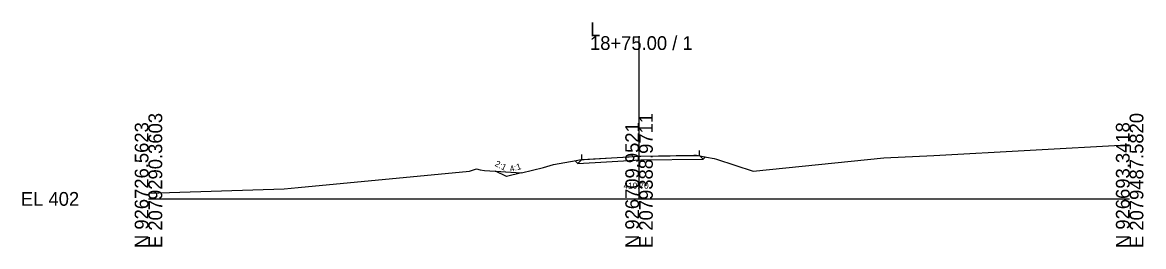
# Model space of a CAD drawing. Extents: x -26 to 10503, y -10 to 9546.
# Drawn here: x 974.3 to 1202.8, y 7490.3 to 7535.9 of the extents above; entities that cross this region are included whole.
import ezdxf

# ---------------------------------------------------------------- set-up
doc = ezdxf.new("R2010")
doc.units = 0
for name, color, linetype in [('Default', 7, 'Continuous'), ('Exist XS Center Line Elevation Label', 7, 'Continuous'), ('Exist XS Ground Line', 7, 'Continuous'), ('Old_Level_63', 7, 'Continuous'), ('Old_Level_8', 7, 'Continuous'), ('Prop XS DDE', 7, 'Continuous'), ('Prop XS EOT Tick Mark', 7, 'Continuous'), ('Prop XS Finish Grade Pavement', 7, 'Continuous'), ('Prop XS Side Slope Text', 7, 'Continuous'), ('Prop XS Subgrade Earthwork', 7, 'Continuous')]:
    doc.layers.add(name, color=color, linetype=linetype)

msp = doc.modelspace()

# ---------------------------------------------------------------- linework, layer by layer
at = {"layer": 'Default'}
for points in [[(1072.96, 7504.55), (1070.72, 7505.67), (1076.03, 7505.32)], [(1076.03, 7505.32), (1072.96, 7504.55), (1070.72, 7505.67)]]:
    msp.add_lwpolyline(points, close=True, dxfattribs=at)
at = {"layer": 'Exist XS Ground Line'}
for p, q in [((1160.07, 7508.82), (1199.33, 7511.01)), ((1199.33, 7511.01), (1200, 7511.03)), ((1082.56, 7507), (1087.18, 7507.8)), ((1087.18, 7507.8), (1088.19, 7507.99)), ((1088.19, 7507.99), (1088.84, 7508.03)), ((1088.84, 7508.03), (1100, 7508.7)), ((1100, 7508.7), (1100.33, 7508.72)), ((1100.33, 7508.72), (1111.14, 7508.89)), ((1111.14, 7508.89), (1111.73, 7508.9)), ((1111.73, 7508.9), (1113.78, 7508.51)), ((1113.78, 7508.51), (1115.32, 7508.23)), ((1115.32, 7508.23), (1115.76, 7508.07)), ((1115.76, 7508.07), (1123.24, 7505.63)), ((1123.24, 7505.63), (1149.87, 7508.36)), ((1149.87, 7508.36), (1160.07, 7508.82)), ((1030.53, 7502.31), (1065.43, 7505.64)), ((1065.43, 7505.64), (1066.86, 7506.1)), ((1066.86, 7506.1), (1067.64, 7505.88)), ((1067.64, 7505.88), (1068.52, 7505.81)), ((1068.52, 7505.81), (1076.03, 7505.32)), ((1076.03, 7505.32), (1080.52, 7506.38)), ((1080.52, 7506.38), (1082.56, 7507)), ((1000, 7501.17), (1027.63, 7502.04)), ((1027.63, 7502.04), (1030.53, 7502.31))]:
    msp.add_line(p, q, dxfattribs=at)
at = {"layer": 'Old_Level_63'}
for p, q in [((1100, 7500), (1100, 7533.1)), ((1000, 7500), (1100, 7500)), ((1100, 7500), (1200, 7500))]:
    msp.add_line(p, q, dxfattribs=at)
at = {"layer": 'Old_Level_8'}
for p, q in [((1088.33, 7508), (1087.53, 7507.2)), ((1112.33, 7508.84), (1113.07, 7508.1))]:
    msp.add_line(p, q, dxfattribs=at)
at = {"layer": 'Prop XS DDE'}
for p, q in [((1072.96, 7504.55), (1070.72, 7505.67)), ((1076.03, 7505.32), (1072.96, 7504.55))]:
    msp.add_line(p, q, dxfattribs=at)
at = {"layer": 'Prop XS EOT Tick Mark'}
for p, q in [((1112.33, 7508.84), (1112.33, 7509.84)), ((1088.33, 7508), (1088.33, 7509))]:
    msp.add_line(p, q, dxfattribs=at)
at = {"layer": 'Prop XS Finish Grade Pavement'}
for p, q in [((1088.33, 7508), (1100.33, 7508.72)), ((1100.33, 7508.72), (1112.33, 7508.84))]:
    msp.add_line(p, q, dxfattribs=at)
at = {"layer": 'Prop XS Subgrade Earthwork'}
for p, q in [((1087.53, 7507.2), (1086.96, 7507.76)), ((1087.53, 7507.2), (1100.37, 7507.97)), ((1100.37, 7507.97), (1113.07, 7508.1)), ((1113.07, 7508.1), (1113.54, 7508.56))]:
    msp.add_line(p, q, dxfattribs=at)

# ---------------------------------------------------------------- texts
at = {"layer": 'Exist XS Center Line Elevation Label'}
msp.add_text('410.70', height=1.25, rotation=360, dxfattribs=at).set_placement((1096.84, 7502.07))
at = {"layer": 'Old_Level_63'}
for s, p in [('L', (1090, 7533.1)), ('18+75.00 / 1', (1090, 7530.3)), ('EL 402', (974, 7498.6))]:
    msp.add_text(s, height=2.8, dxfattribs=at).set_placement(p)
for s, p in [('E 2079290.3603', (1002.8, 7490)), ('E 2079388.9711', (1102.8, 7490)), ('E 2079487.5820', (1202.8, 7490)), ('N 926726.5623', (1000, 7490)), ('N 926709.9521', (1100, 7490)), ('N 926693.3418', (1200, 7490))]:
    msp.add_text(s, height=2.8, rotation=90, dxfattribs=at).set_placement(p)
at = {"layer": 'Prop XS Side Slope Text'}
for s, rotation, p in [('2:1', 333.4349, (1070.5, 7506.76)), ('4:1', 15.4834, (1073.83, 7505.47))]:
    msp.add_text(s, height=1.25, rotation=rotation, dxfattribs=at).set_placement(p)

doc.saveas('drawing.dxf')
